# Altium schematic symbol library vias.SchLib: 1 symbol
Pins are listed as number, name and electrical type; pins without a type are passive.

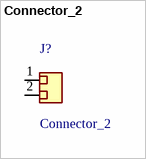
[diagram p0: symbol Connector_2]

## Connector_2
designator J?
Generic two-circuit connector
pins: 1 Passive, 2 Passive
